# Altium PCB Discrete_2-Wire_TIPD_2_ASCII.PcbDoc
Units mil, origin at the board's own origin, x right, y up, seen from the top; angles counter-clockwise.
Board outline 1600 x 900 mil, 2 copper layers (Top Layer, Bottom Layer), stack 62 mil thick; 27 components, 16 nets, 69 pads, 21 vias.
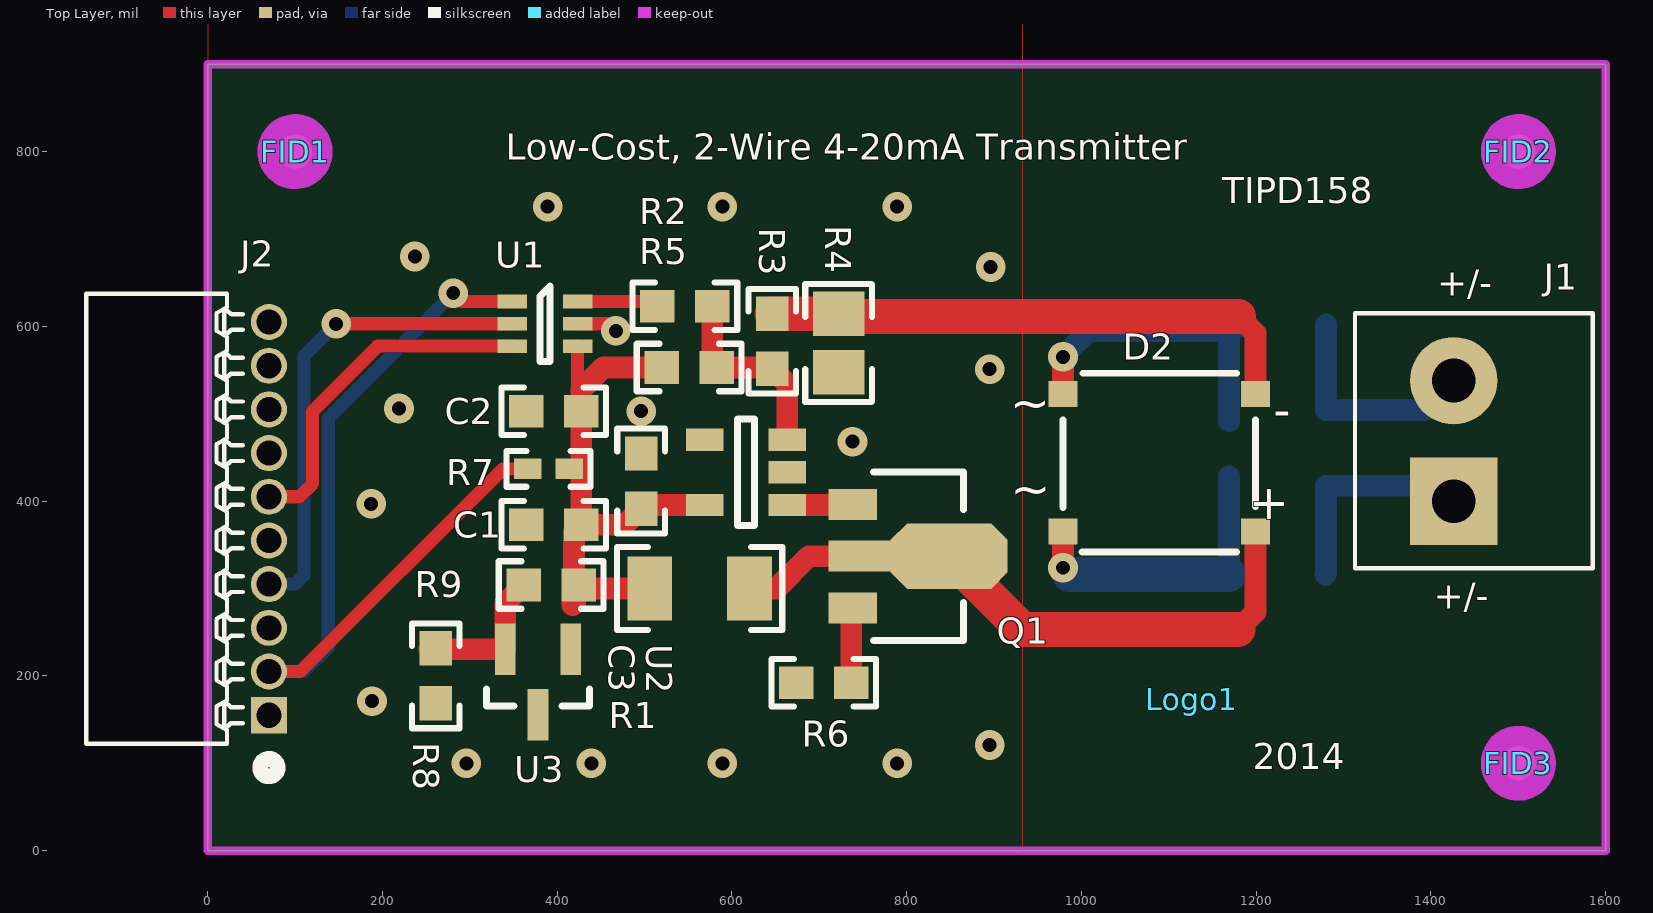
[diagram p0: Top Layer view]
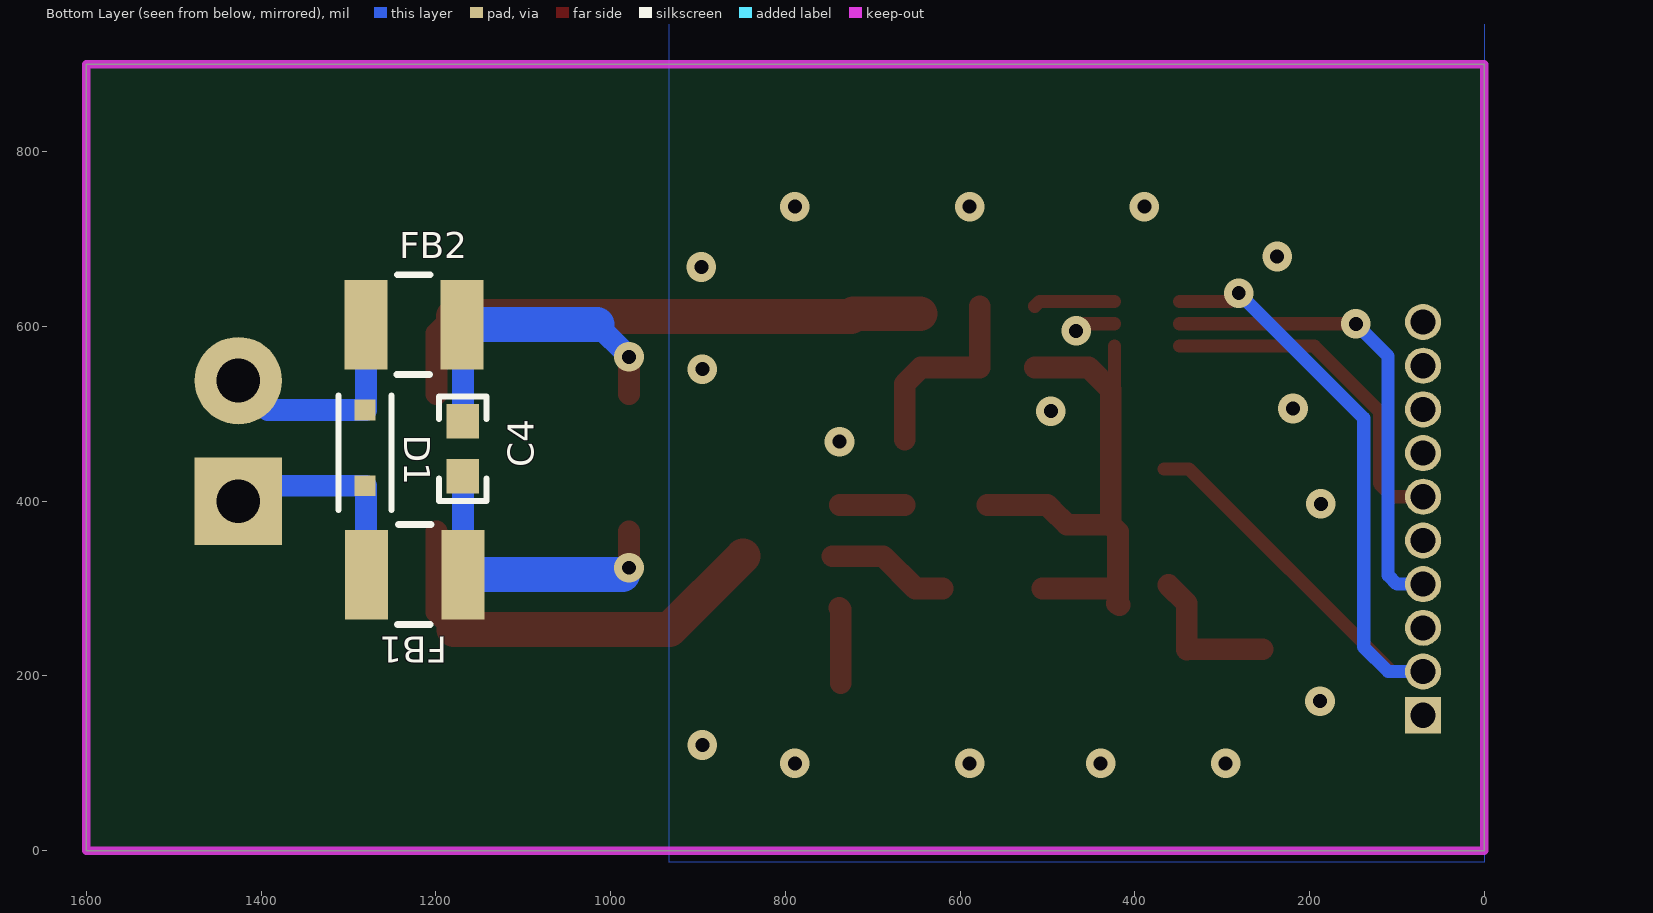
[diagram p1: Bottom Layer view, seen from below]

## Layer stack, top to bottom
Top Layer: signal copper 1.4
Dielectric: core 59.2, FR-4, Dk 4.8
Bottom Layer: signal copper 1.4

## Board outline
0,0 1600,0 1600,900 0,900

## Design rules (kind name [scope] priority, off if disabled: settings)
AcuteAngle [All] p0: scope1count=1 scope1_0_kind=Board scope1_0_value=Board scope2count=1 scope2_0_kind=Board scope2_0_value=Board commentlength=0 minimum=4.50000000000000E+0001
AcuteAngle [All] p1: minimum=4.50000000000000E+0001 checktracksonly=FALSE
AssemblyTestPointUsage [All] p0: scope1count=1 scope1_0_kind=Board scope1_0_value=Board scope2count=1 scope2_0_kind=Board scope2_0_value=Board commentlength=0
AssemblyTestPointUsage [All] p1: valid=2
AssemblyTestpoint [All] p0: scope1count=1 scope1_0_kind=Board scope1_0_value=Board scope2count=1 scope2_0_kind=Board scope2_0_value=Board commentlength=0
Clearance [All] p0: scope1count=1 scope1_0_kind=Board scope1_0_value=Board scope2count=1 scope2_0_kind=Board scope2_0_value=Board commentlength=0 gap=8
Clearance Clearance_Poly [All] p0 off: scope1count=1 scope1_0_kind=Board scope1_0_value=Board scope2count=1 scope2_0_kind=Board scope2_0_value=Board commentlength=48 gap=10 // Protel DXP Scope 1 Expression Was: InPolygon
Clearance Clearance_BoardEdge [All] p0 off: scope1count=1 scope1_0_kind=Board scope1_0_value=Board scope2count=1 scope2_0_kind=Board scope2_0_value=Board commentlength=48 gap=75 // Protel DXP Scope 2 Expression Was: IsKeepOut
Clearance Clearance_BoardEdge_Poly [All] p0 off: scope1count=1 scope1_0_kind=Board scope1_0_value=Board scope2count=1 scope2_0_kind=Board scope2_0_value=Board commentlength=48 gap=25 // Protel DXP Scope 2 Expression Was: IsKeepOut
Clearance Clearance_BoardEdge_MountingHoles [All] p0 off: scope1count=1 scope1_0_kind=Board scope1_0_value=Board scope2count=1 scope2_0_kind=Board scope2_0_value=Board commentlength=48 gap=40 // Protel DXP Scope 2 Expression Was: IsKeepOut
Clearance Clearance_BoardEdge_MountingHoles [OnCopper and InComponentClass('Mounting Holes') vs IsKeepOut] p1: gap=40
Clearance Clearance_BoardEdge_Poly [OnCopper and InPoly vs IsKeepOut] p2: gap=25
Clearance Clearance_BoardEdge [OnCopper and Not InComponentClass('Logo') and not InComponentClass('FiducialMark') and not InRegion(1000,500,4000,800) and Not IsKeepout vs IsKeepOut] p3: gap=75
Clearance Clearance_Poly [InPolygon] p4: gap=10
Clearance [All] p5: gap=8
ComponentClearance [All] p0: scope1count=1 scope1_0_kind=Board scope1_0_value=Board scope2count=1 scope2_0_kind=Board scope2_0_value=Board commentlength=0 gap=40 collisioncheckmode=3
ComponentClearance ComponentClearance_THtoTH [All] p0 off: scope1count=1 scope1_0_kind=Board scope1_0_value=Board scope2count=1 scope2_0_kind=Board scope2_0_value=Board commentlength=54 gap=118.11 collisioncheckmode=3 // Protel DXP Scope 2 Expression Was: IsThruComponent
ComponentClearance ComponentClearance_THtoSMT [All] p0 off: scope1count=1 scope1_0_kind=Board scope1_0_value=Board scope2count=1 scope2_0_kind=Board scope2_0_value=Board commentlength=53 gap=100 collisioncheckmode=3 // Protel DXP Scope 2 Expression Was: IsSMTComponent
ComponentClearance ComponentClearance_SmallPassives [All] p0 off: scope1count=1 scope1_0_kind=Board scope1_0_value=Board scope2count=1 scope2_0_kind=Board scope2_0_value=Board commentlength=508 gap=20 collisioncheckmode=3 // Protel DXP Scope 2 Expression Was: HasFootprint('0201*') or HasFootprint('0402*') or HasFootprint('0508') or HasFootprint('0603*') or HasFootprint('0612') or HasFootprint('0805*') or HasFootprint('0815*') or HasFootprint('0830*') or HasFootprint('1206*') or HasFootprint('1210*') or HasFootprint('1808*') or HasFootprint('1812*') or HasFootprint('1825*') or HasFootprint('2010*') or HasFootprint('2220*') or HasFootprint('2225*') or HasFootprint('2512*') or HasFootprint('2728*') or HasFootprint('3518*')
ComponentClearance ComponentClearance_MountingHoles [All] p0: scope1count=1 scope1_0_kind=ComponentClass scope1_0_value="Mounting Holes" scope2count=1 scope2_0_kind=Board scope2_0_value=Board commentlength=0 gap=250 collisioncheckmode=3
ComponentClearance ComponentClearance_ScrewToNut [All] p0 off: scope1count=1 scope1_0_kind=Board scope1_0_value=Board scope2count=1 scope2_0_kind=Board scope2_0_value=Board commentlength=71 gap=5 collisioncheckmode=3 // Protel DXP Scope 2 Expression Was: (HasFootprint('Keystone_1902C'))
ComponentClearance ComponentClearance_Logo [All] p0: scope1count=1 scope1_0_kind=ComponentClass scope1_0_value=Logo scope2count=1 scope2_0_kind=Board scope2_0_value=Board commentlength=0 gap=50 collisioncheckmode=3
ComponentClearance ComponentClearance_Shunt [All] p0: scope1count=1 scope1_0_kind=ComponentClass scope1_0_value=Header scope2count=1 scope2_0_kind=ComponentClass scope2_0_value=Shunt commentlength=0 gap=0 collisioncheckmode=3
ComponentClearance ComponentClearance_Shunt [InComponentClass('Header') vs InComponentClass('Shunt')] p1: gap=0 collisioncheckmode=3 verticalgap=0 showdistances=FALSE
ComponentClearance ComponentClearance_Logo [InComponentClass('Logo')] p2: gap=50 collisioncheckmode=3 verticalgap=10 showdistances=FALSE
ComponentClearance ComponentClearance_ScrewToNut [(HasFootprint('NY PMS 440 0025 PH')) vs (HasFootprint('Keystone_1902C'))] p3: gap=5 collisioncheckmode=3 verticalgap=10 showdistances=FALSE
ComponentClearance ComponentClearance_MountingHoles [InComponentClass('Mounting Holes')] p4: gap=250 collisioncheckmode=3 verticalgap=100000 showdistances=FALSE
ComponentClearance ComponentClearance_SmallPassives [HasFootprint('0201*') or HasFootprint('0402*') or HasFootprint('0508') or HasFootprint('0603*') or HasFootprint('0612') or HasFootprint('0805*') or HasFootprint('0815*') or HasFootprint('0830*') or HasFootprint('1206*') or HasFootprint('1210*') or HasFootprint('1808*') or HasFootprint('1812*') or HasFootprint('1825*') or HasFootprint('2010*') or HasFootprint('2220*') or HasFootprint('2225*') or HasFootprint('2512*') or HasFootprint('2728*') or HasFootprint('3518*') vs HasFootprint('0201*') or HasFootprint('0402*') or HasFootprint('0508') or HasFootprint('0603*') or HasFootprint('0612') or HasFootprint('0805*') or HasFootprint('0815*') or HasFootprint('0830*') or HasFootprint('1206*') or HasFootprint('1210*') or HasFootprint('1808*') or HasFootprint('1812*') or HasFootprint('1825*') or HasFootprint('2010*') or HasFootprint('2220*') or HasFootprint('2225*') or HasFootprint('2512*') or HasFootprint('2728*') or HasFootprint('3518*')] p5: gap=20 collisioncheckmode=3 verticalgap=10 showdistances=FALSE
ComponentClearance ComponentClearance_THtoSMT [IsThruComponent vs IsSMTComponent] p6: gap=100 collisioncheckmode=3 verticalgap=30 showdistances=FALSE
ComponentClearance ComponentClearance_THtoTH [IsThruComponent vs IsThruComponent] p7: gap=118.11 collisioncheckmode=3 verticalgap=30 showdistances=FALSE
ComponentClearance [All] p8: gap=40 collisioncheckmode=3 verticalgap=10 showdistances=FALSE
DiffPairsRouting [All] p0: scope1count=1 scope1_0_kind=Board scope1_0_value=Board scope2count=1 scope2_0_kind=Board scope2_0_value=Board commentlength=0
DiffPairsRouting [All] p1: maxlimit=100 minlimit=10 mostfreqgap=10 maxuncoupledlength=1000
FabricationTestPointUsage TestPointUsage [All] p0: scope1count=1 scope1_0_kind=Board scope1_0_value=Board scope2count=1 scope2_0_kind=Board scope2_0_value=Board commentlength=0 valid=2 allowmultiple=FALSE
FabricationTestPointUsage TestPointUsage [All] p1: valid=2 allowmultiple=FALSE
FabricationTestpoint Testpoint [All] p0: scope1count=1 scope1_0_kind=Board scope1_0_value=Board scope2count=1 scope2_0_kind=Board scope2_0_value=Board commentlength=0 side=3 testpointundercomponent=TRUE minsize=40 maxsize=100 preferedsize=60 minholesize=0 maxholesize=40 preferedholesize=32 testpointgrid=1
FabricationTestpoint Testpoint [All] p1: side=3 testpointundercomponent=TRUE minsize=40 maxsize=100 preferedsize=60 minholesize=0 maxholesize=40 preferedholesize=32 testpointgrid=1 allowsidetop=TRUE allowsidebottom=TRUE usegrid=TRUE gridtolerance=0.01
FanoutControl Fanout_Small [All] p0 off: scope1count=1 scope1_0_kind=Board scope1_0_value=Board scope2count=1 scope2_0_kind=Board scope2_0_value=Board commentlength=84 // Protel DXP Scope 1 Expression Was: (CompPinCount < 5)   Fanout_Small (Default Rule)
FanoutControl Fanout_Default [All] p0: scope1count=1 scope1_0_kind=Board scope1_0_value=Board scope2count=1 scope2_0_kind=Board scope2_0_value=Board commentlength=30 // Fanout_Default (Default Rule)
FanoutControl Fanout_SOIC [All] p0 off: scope1count=1 scope1_0_kind=Board scope1_0_value=Board scope2count=1 scope2_0_kind=Board scope2_0_value=Board commentlength=71 // Protel DXP Scope 1 Expression Was: IsSOIC   Fanout_SOIC (Default Rule)
FanoutControl Fanout_BGA [All] p0 off: scope1count=1 scope1_0_kind=Board scope1_0_value=Board scope2count=1 scope2_0_kind=Board scope2_0_value=Board commentlength=69 // Protel DXP Scope 1 Expression Was: IsBGA   Fanout_BGA (Default Rule)
FanoutControl Fanout_LCC [All] p0 off: scope1count=1 scope1_0_kind=Board scope1_0_value=Board scope2count=1 scope2_0_kind=Board scope2_0_value=Board commentlength=69 // Protel DXP Scope 1 Expression Was: IsLCC   Fanout_LCC (Default Rule)
FanoutControl Fanout_LCC [IsLCC] p1: bgadir=Out bgaviamode=Centered fanoutstyle=Auto fanoutdirection=Alternating viagrid=1 // Fanout_LCC (Default Rule)
FanoutControl Fanout_BGA [IsBGA] p2: bgadir=Out bgaviamode=Centered fanoutstyle=Auto fanoutdirection=Alternating viagrid=1 // Fanout_BGA (Default Rule)
FanoutControl Fanout_Default [All] p4: bgadir=Out bgaviamode=Centered fanoutstyle=Auto fanoutdirection=Alternating viagrid=1 // Fanout_Default (Default Rule)
FanoutControl Fanout_Small [(CompPinCount < 5)] p5: bgadir=Out bgaviamode=Centered fanoutstyle=Auto fanoutdirection=OutThenIn viagrid=1 // Fanout_Small (Default Rule)
Height [All] p0: scope1count=1 scope1_0_kind=Board scope1_0_value=Board scope2count=1 scope2_0_kind=Board scope2_0_value=Board commentlength=0
HoleSize [All] p0: scope1count=1 scope1_0_kind=Board scope1_0_value=Board scope2count=1 scope2_0_kind=Board scope2_0_value=Board commentlength=0 absolutevalues=TRUE maxlimit=251 minlimit=8 maxpercent=80.000 minpercent=20.000
HoleSize [All] p1: absolutevalues=TRUE maxlimit=251 minlimit=8 maxpercent=80.000 minpercent=20.000
HoleToHoleClearance [All] p0: scope1count=1 scope1_0_kind=Board scope1_0_value=Board scope2count=1 scope2_0_kind=Board scope2_0_value=Board commentlength=0
LayerPairs [All] p0: scope1count=1 scope1_0_kind=Board scope1_0_value=Board scope2count=1 scope2_0_kind=Board scope2_0_value=Board commentlength=0 enforce=TRUE
MinimumAnnularRing [All] p0: scope1count=1 scope1_0_kind=Board scope1_0_value=Board scope2count=1 scope2_0_kind=Board scope2_0_value=Board commentlength=0 minimumring=9
MinimumAnnularRing MinimumAnnularRing_ThermalPadVias [All] p0 off: scope1count=1 scope1_0_kind=Board scope1_0_value=Board scope2count=1 scope2_0_kind=Board scope2_0_value=Board commentlength=63 minimumring=5.91 // Protel DXP Scope 1 Expression Was: IsVia and InAnyComponent
MinimumAnnularRing MinimumAnnularRing_ThermalPadVias [IsVia and InAnyComponent] p1: minimumring=5.91
MinimumAnnularRing [All] p2: minimumring=9
MinimumSolderMaskSliver [All] p0: scope1count=1 scope1_0_kind=Board scope1_0_value=Board scope2count=1 scope2_0_kind=Board scope2_0_value=Board commentlength=0
MinimumSolderMaskSliver MinimumSolderMaskSliver_Logo [All] p0: scope1count=1 scope1_0_kind=ComponentClass scope1_0_value=Logo scope2count=1 scope2_0_kind=ComponentClass scope2_0_value=Logo commentlength=0
MinimumSolderMaskSliver MinimumSolderMaskSliver_Logo [InComponentClass('Logo') vs InComponentClass('Logo')] p1: minsoldermaskwidth=0.7
MinimumSolderMaskSliver [All] p2: minsoldermaskwidth=3.94
NetAntennae [All] p0: scope1count=1 scope1_0_kind=Board scope1_0_value=Board scope2count=1 scope2_0_kind=Board scope2_0_value=Board commentlength=0
PasteMaskExpansion [All] p0: scope1count=1 scope1_0_kind=Board scope1_0_value=Board scope2count=1 scope2_0_kind=Board scope2_0_value=Board commentlength=0 expansion=0
PlaneClearance [All] p0: scope1count=1 scope1_0_kind=Board scope1_0_value=Board scope2count=1 scope2_0_kind=Board scope2_0_value=Board commentlength=0 clearance=10
PlaneClearance [All] p1: clearance=10
PlaneConnect [All] p0: scope1count=1 scope1_0_kind=Board scope1_0_value=Board scope2count=1 scope2_0_kind=Board scope2_0_value=Board commentlength=0 planeconnectstyle=Relief reliefexpansion=10 reliefentries=4 reliefconductorwidth=10 reliefairgap=10
PlaneConnect [All] p1: planeconnectstyle=Relief reliefexpansion=10 reliefentries=4 reliefconductorwidth=10 reliefairgap=10
PolygonConnect PolygonConnect_1 [All] p0 off: scope1count=1 scope1_0_kind=Board scope1_0_value=Board scope2count=1 scope2_0_kind=Board scope2_0_value=Board commentlength=75 connectstyle=Relief reliefconductorwidth=15 reliefentries=4 polygonreliefangle="90 Angle" // Protel DXP Scope 1 Expression Was: (InComponentClass('All Components'))
PolygonConnect [All] p0: scope1count=1 scope1_0_kind=Board scope1_0_value=Board scope2count=1 scope2_0_kind=Board scope2_0_value=Board commentlength=0 connectstyle=Direct reliefconductorwidth=10 reliefentries=4 polygonreliefangle="90 Angle"
PolygonConnect PolygonConnect_1 [(InComponentClass('All Components'))] p1: connectstyle=Relief reliefconductorwidth=15 reliefentries=4 polygonreliefangle="90 Angle" airgapwidth=10
PolygonConnect [All] p2: connectstyle=Direct reliefconductorwidth=10 reliefentries=4 polygonreliefangle="90 Angle" airgapwidth=10
RoutingCorners [All] p0: scope1count=1 scope1_0_kind=Board scope1_0_value=Board scope2count=1 scope2_0_kind=Board scope2_0_value=Board commentlength=0 cornerstyle=45-Degree minsetback=100 maxsetback=100
RoutingLayers [All] p0: scope1count=1 scope1_0_kind=Board scope1_0_value=Board scope2count=1 scope2_0_kind=Board scope2_0_value=Board commentlength=0 top layer=Automatic bottom layer=Automatic
RoutingPriority [All] p0: scope1count=1 scope1_0_kind=Board scope1_0_value=Board scope2count=1 scope2_0_kind=Board scope2_0_value=Board commentlength=0
RoutingTopology [All] p0: scope1count=1 scope1_0_kind=Board scope1_0_value=Board scope2count=1 scope2_0_kind=Board scope2_0_value=Board commentlength=0 topology=Shortest
RoutingVias [All] p0: scope1count=1 scope1_0_kind=Board scope1_0_value=Board scope2count=1 scope2_0_kind=Board scope2_0_value=Board commentlength=0 holewidth=16 width=34 viastyle="Through Hole" minholewidth=7.87 minwidth=26 maxholewidth=40 maxwidth=65
RoutingVias ThermalPadVias [All] p0 off: scope1count=1 scope1_0_kind=Board scope1_0_value=Board scope2count=1 scope2_0_kind=Board scope2_0_value=Board commentlength=63 holewidth=7.87 width=19.68 viastyle="Through Hole" minholewidth=7.87 minwidth=19.68 maxholewidth=12.99 maxwidth=23.62 // Protel DXP Scope 1 Expression Was: IsVia and InAnyComponent
RoutingVias ThermalPadVias [IsVia and InAnyComponent] p1: holewidth=7.87 width=19.68 viastyle="Through Hole" minholewidth=7.87 minwidth=19.68 maxholewidth=12.99 maxwidth=23.62
RoutingVias [All] p2: holewidth=16 width=34 viastyle="Through Hole" minholewidth=7.87 minwidth=26 maxholewidth=40 maxwidth=65
SMDToCorner [All] p0: scope1count=1 scope1_0_kind=Board scope1_0_value=Board scope2count=1 scope2_0_kind=Board scope2_0_value=Board commentlength=0 distance=30000
SMDToCorner [All] p1: distance=30000
ShortCircuit [All] p0: scope1count=1 scope1_0_kind=Board scope1_0_value=Board scope2count=1 scope2_0_kind=Board scope2_0_value=Board commentlength=0 allowed=FALSE
SilkToSilkClearance [All] p0: scope1count=1 scope1_0_kind=Board scope1_0_value=Board scope2count=1 scope2_0_kind=Board scope2_0_value=Board commentlength=0
SilkToSilkClearance [All] p1: silktosilkclearance=5
SilkscreenOverComponentPads [All] p0: scope1count=1 scope1_0_kind=Board scope1_0_value=Board scope2count=1 scope2_0_kind=Board scope2_0_value=Board commentlength=0
SilkscreenOverComponentPads [All] p1: minsilkscreentomaskgap=5
SolderMaskExpansion [All] p0: scope1count=1 scope1_0_kind=Board scope1_0_value=Board scope2count=1 scope2_0_kind=Board scope2_0_value=Board commentlength=0 expansion=1.97
SolderMaskExpansion [All] p1: expansion=1.97
UnRoutedNet [All] p0: scope1count=1 scope1_0_kind=Board scope1_0_value=Board scope2count=1 scope2_0_kind=Board scope2_0_value=Board commentlength=0
Width [All] p0: scope1count=1 scope1_0_kind=Board scope1_0_value=Board scope2count=1 scope2_0_kind=Board scope2_0_value=Board commentlength=0 maxlimit=100 minlimit=6 preferedwidth=10
Width [All] p1: maxlimit=100 minlimit=6 preferedwidth=10 checkconnectedcopper=TRUE
13 further rules are at their usual default settings.

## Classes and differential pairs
component class Discrete_2-Wire_AO_2: C1 C2 C3 C4 D1 D2 FB1 FB2 J1 J2 Q1 R1 R2 R3 R4 R5 R6 R7 R8 U1 U2 U3
component class FiducialMark: FID1 FID2 FID3
component class Hardware_ANSI-B: FID1 FID2 FID3 Logo1
component class Logo: Logo1

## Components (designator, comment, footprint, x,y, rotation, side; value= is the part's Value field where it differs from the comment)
C1 "CC0603ZRY5V6BB225" 0603 396.02,373 r180 top
C2 "CC0603KRX7R0BB104" 0603 396.02,503 r180 top
C3 "CC0603KRX7R0BB104" 0603 496.02,423 r90 top
C4 "C1608X7R2A472K080AA" 0603 1169,460 r90 bottom
D1 "CDSOD323-T36SC" sod-323 1281,461 r90 bottom
D2 "DSRHD10-13" T-MiniDIP 1089,444 r180 top
FB1 "FBMH3225HM601NT" 1210_H25 1224,316 r0 bottom
FB2 "FBMH3225HM601NT" 1210_H25 1225,602 r0 bottom
FID1 "Fiducial" Fiducial10-20 100,800 r0 top
FID2 "Fiducial" Fiducial10-20 1500,800 r0 top
FID3 "Fiducial" Fiducial10-20 1500,100 r0 top
J1 "ED555/2DS" TERM_BLK_ED555-2DS 1426,400 r90 top
J2 "SUPER MINI DIG FEMALE" CONN_851-43-010-20-001000 70,380 r270 top
Logo1 "Texas Instruments" TI_Symbol_Overlay_Small 1126,173 r0 top
Q1 "FCX690BTA" SOT-89-3 813,337 r0 top
R1 "RC1206FR-077K15L" 1206 563,300 r180 top
R2 "ERA-3AEB3092V" 0603 546.02,623 r0 top
R3 "ERA-3AEB4321V" 0603 646.02,583 r270 top
R4 "RP73PF2A44R2BTDF" 0805 722,581 r270 top
R5 "ERA-3AEB1243V" 0603 551,553 r180 top
R6 "CRCW060320R0FKEA" 0603 705,192 r0 top
R7 "CRCW040210K0FKED" 0402 390,437 r0 top
R8 "TNPW060324K9BEEA" 0603 393,304 r0 top
R9 "TNPW060324K9BEEA" 0603 261,200 r90 top
U1 "DAC7311IDCK" DCK0006A_N 386.02,603 r0 top
U2 "OPA317IDBV" DBV0005A_N 616.02,433 r180 top
U3 "TL431BQDBZ" DBZ0003A_N 378,193 r270 top

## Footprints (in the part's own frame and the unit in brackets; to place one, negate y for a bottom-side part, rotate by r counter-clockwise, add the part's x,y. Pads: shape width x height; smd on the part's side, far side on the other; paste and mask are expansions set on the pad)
0402 [mm] "0402 from SM-752 data"
  rect 0.8x0.6 smd: 1(-0.6,0) 2(0.6,0)
  silkscreen extent -1.22,-0.52 1.22,0.52
0603 [mm] "0603 from SM-752 data"
  rect 1x0.95 smd: 1(-0.8,0) 2(0.8,0)
  silkscreen extent -1.52,-0.69 1.52,0.69
0805 [mm] "0805 from SM-752 data"
  rect 1.3x1.5 smd: 1(-0.85,0) 2(0.85,0)
  silkscreen extent -1.72,-0.97 1.72,0.97
1206 [mm] "1206 from SM-752 data"
  rect 1.3x1.85 smd: 1(-1.45,0) 2(1.45,0)
  silkscreen extent -2.4,-1.21 2.4,1.21
1210_H25 [mm]
  rect 1.25x2.6 smd: 1(-1.4,0) 2(1.4,0)
  silkscreen extent -0.47,-1.45 0.5,1.45
CONN_851-43-010-20-001000 [mm] "Mill-max"
  rect 1.05x1.05 hole 0.73 mask+0.06: 1(5.715,0)
  round 1.05 hole 0.73 mask+0.06: 2(4.445,0) 3(3.175,0) 4(1.905,0) 5(0.635,0) 6(-0.635,0) 7(-1.905,0) 8(-3.175,0) 9(-4.445,0) 10(-5.715,0)
  silkscreen extent -6.54,-5.31 7.49,0.25
DBV0005A_N [mm] "SOT23, 5-Leads, Body 2.9x1.6mm, Pitch 0.95mm, Lead Span 2.8mm, IPC Medium Density"
  rect 1.1x0.65 smd: 1(-1.2,0.95) 2(-1.2,0) 3(-1.2,-0.95) 4(1.2,-0.95) 5(1.2,0.95)
  silkscreen extent -0.25,-1.55 0.25,1.55
DBZ0003A_N [mm] "SOT23, 3-Leads, Body 2.9x1.3mm, Pitch 0.95mm, Lead Span 2.4mm, IPC Medium Density"
  rect 1.5x0.6 smd: 1(-0.95,0.95) 2(-0.95,-0.95) 3(0.95,0)
  silkscreen extent 0.2,-1.5 0.7,1.5
DCK0006A_N [mm] "SOT23, 6-Leads, Body 2x1.3mm, Pitch 0.65mm, Lead Span 2.1mm, IPC Medium Density"
  rect 0.85x0.4 smd: 1(-0.95,0.65) 2(-0.95,0) 3(-0.95,-0.65) 4(0.95,-0.65) 5(0.95,0) 6(0.95,0.65)
  silkscreen extent -0.15,-1.1 0.15,1.1
Fiducial10-20 [mm]
  round 1 smd paste-0.5 mask+0.5: 1(0,0)
  Top Layer keep-out circle w1.178: c0,0 r0.5
sod-323 [mm] "NXP recommended land pattern"
  rect 0.6x0.6 smd paste-0.05: 1(-1.1,0) 2(1.1,0)
  silkscreen extent -1.8,-0.77 1.53,0.77
SOT-89-3 [mm] "SOT, 3-Leads, Body 4.6 x 2.6 mm, Pitch 1.5mm"
  rect 1.4x0.9 smd: 1(-1.9,1.5) 3(-1.9,-1.5)
  rect 1.8x0.9 smd: 2(-1.7,0)
  oct 3.4x1.9 smd: 4(0.9,0)
  silkscreen extent -1.3,-2.45 1.33,2.45
T-MiniDIP [mm] "DIODES INC"
  rect 0.85x0.75 smd: 1(-2.8,2) 2(-2.8,-2) 3(2.8,-2) 4(2.8,2)
  silkscreen extent -2.8,-2.6 2.8,2.6
TERM_BLK_ED555-2DS [mil]
  rect 100x100 hole 50: 1(0,0)
  round 100 hole 50: 2(138,0)
  silkscreen extent -77,-159 215,113
TI_Symbol_Overlay_Small [mil]

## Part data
C1: library part Capacitor, "CAP CER 2.2UF 10V Y5V 0603"
C2 C3: library part Capacitor, "CAP CER 0.1UF 100V 10% X7R 0603"
C4: library part Capacitor, "CAP CER 4700PF 100V 10% X7R 0603"
D1: library part SMAJ15CA, "TVS DIODE 36VWM 60VC SOD323"
D2: "Diode, Switching-Bridge, 1000V, 1A, 5.0x1.21x6.2mm"
FB1 FB2: "3A Ferrite Bead, 600 ohm @ 100MHz, SMD"
FID1 FID2 FID3: "Fiducial mark.  There is nothing to buy or mount."
J1: "Terminal Block, 6A, 3.5mm Pitch, 2-Pos, TH"
J2: library part 851-43-010-20-001000, "Receptacle, 50mil 10x1, R/A, TH"
Logo1: library part TI_Logo, "Texas Instrument Corporate Signature"
Q1: library part "FCX690BTA, Diodes Inc.", "Transistor, NPN, 45V, 1A, SOT-89"
R1: library part Resistor, "RES 7.15K OHM 1/4W 1% 1206 SMD"
R2: library part Resistor, "RES 30.9K OHM 1/10W .1% 0603 SMD"
R3: library part Resistor, "RES 4.32K OHM 1/10W .1% 0603 SMD"
R4: library part Resistor, "RES 44.2 OHM 1/4W 0.1% 0805"
R5: library part Resistor, "RES 124K OHM 1/10W .1% 0603 SMD"
R6: "RES, 20.0 ohm, 1%, 0.1W, 0603"
R7: "RES, 10.0k ohm, 1%, 0.063W, 0402"
R8 R9: library part Resistor, "RES 24.9K OHM 1/10W 0.1% 0603"
U1: "2.0V to 5.5V, 80µA, 12-Bit, Low-Power, Single-Channel, Digital-to-Analog Converters in SC70 Package, DCK0006A"
U2: "Low-Offset, Rail-to-Rail I/O Operational Amplifier, DBV0005A"
U3: "PRECISION PROGRAMMABLE REFERENCE, DBZ0003A"

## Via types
v1: diameter 34, hole 16, Top Layer to Bottom Layer, 21 vias

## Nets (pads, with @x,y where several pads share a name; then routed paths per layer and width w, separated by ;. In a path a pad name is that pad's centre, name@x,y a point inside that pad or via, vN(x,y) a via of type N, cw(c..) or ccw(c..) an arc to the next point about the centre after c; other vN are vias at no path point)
+5V: C1.1 C2.1 C3.1 R1.2 R5.2 R7.2 R8.2 U1.4 U2.5 U3.1 | length 663.9
  Top Layer w15: U1.4 423.42,507.09 C2.1
  Top Layer w25: 417.62,281.3 419.32,283 ; 420.31,283 419.32,283 ; R1.2 423.32,300 R8.2@419.32,304 ; R5.2@514.52,553 452.82,553 427.51,527.7 C2.1 C1.1 ; U2.5 500.11,395.6 C3.1 477.51,373 C1.1 ; 419.32,283 R8.2@419.32,304 ; R8.2@419.32,304 419.32,364.81 C1.1
GND: C1.2 C2.2 C3.2 J2.3 R4.2 R6.1 R9.1 U1.5 U2.2 U2.4 U3.3 | length 46.9
  Top Layer w15: U1.5 459,603 v1(467,595)
  other v1: 296,100 439,100 589,100 789,100 895,121 188,171 187,397 738,468 496,503 219,506 895,551 896,668 237,680 389,737 589,737 789,737
NetC4_1: C4.1 D2.4 FB1.1 | length 347.4
  Top Layer w25: v1(978.76,323.76) D2.4
  Bottom Layer w25: v1(978.76,323.76) v1@986.53,316 ; FB1.1 1169,316.12 C4.1
  Bottom Layer w40: v1@986.53,316 FB1.1
NetC4_2: C4.2 D2.3 FB2.1 | length 359.7
  Top Layer w25: D2.3 v1(978.76,565.24)
  Bottom Layer w25: v1(978.76,565.24) 1015.53,602 ; C4.2 1169,601.12 FB2.1
  Bottom Layer w40: 1015.53,602 FB2.1
NetD1_1: D1.1 FB1.2 J1.1 | length 301.6
  Top Layer w25: J1.1@1403.31,413.69 J1.1@1419,398
  Bottom Layer w25: FB1.2 1280,316.88 D1.1@1280,417.69 ; D1.1 1408.31,417.69 J1.1 ; J1.1@1401.31,415.69 J1.1@1419,398
NetD1_2: D1.2 FB2.2 J1.2 | length 257.7
  Bottom Layer w25: FB2.2 1280,601.88 1280,504.31 1392.31,504.31 J1.2
NetD2_1: D2.1 Q1.2 Q1.4 R1.1 | length 627.3
  Top Layer w25: R1.1 651,300 688,337 Q1.2 ; 1179,253 1199.24,273.24 D2.1
  Top Layer w40: Q1.4 932.43,253 1179,253
NetD2_2: D2.2 R3.1 R4.1 | length 631.6
  Top Layer w25: 1179.54,611.46 1199.24,591.76 D2.2
  Top Layer w40: R3.1 R4.1 ; R4.1 725,611.46 1179.54,611.46
NetJ2_2: J2.2 R7.1 U1.1 | length 1007.8
  Top Layer w15: J2.2 106,205 338,437 R7.1 ; v1(281,638) 290.41,628.59 U1.1
  Bottom Layer w15: J2.2 110,205 138,233 138,495 v1(281,638)
NetJ2_4: J2.4 U1.2 | length 549.1
  Top Layer w15: v1(147,603) U1.2
  Bottom Layer w15: J2.4 100,305 110,315 110,566 v1(147,603)
NetJ2_6: J2.6 U1.3 | length 381.2
  Top Layer w15: J2.6@87.5,405 105,405 120,420 120,503 194.41,577.41 U1.3
NetQ1_1: Q1.1 U2.1 | length 74.5
  Top Layer w25: U2.1 Q1.1@737.74,395.6
NetQ1_3: Q1.3 R6.2 | length 86.6
  Top Layer w25: R6.2 736.5,276.24 Q1.3
NetR2_1: R2.1 U1.6 | length 93.4
  Top Layer w15: U1.6 508.93,628.59 R2.1
NetR2_2: R2.2 R3.2 R5.1 U2.3 | length 225.3
  Top Layer w25: R2.2 577.51,553 R5.1 R3.2@644.52,553 ; R3.2 663.26,534.26 U2.3
NetR8_1: R8.1 R9.2 U3.2 | length 168.9
  Top Layer w15: U3.2@340.5,230.5 U3.2
  Top Layer w25: R9.2@254,230.5 U3.2@340.5,230.5 ; U3.2 340.6,283.09 R8.1
pads on no net: FID1.1 FID2.1 FID3.1 J2.1 J2.5 J2.7 J2.8 J2.9 J2.10

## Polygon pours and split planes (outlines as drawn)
GND on Bottom Layer "Bottom Layer-No Net" (solid, remove dead copper, pour order 4): 0,-13 933,-13 933,1000 0,1000
GND on Top Layer "Top Layer-No Net" (solid, remove dead copper, pour order 2): 0,-1 933,-1 933,1000 0,1000

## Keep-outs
Keep-Out Layer:
  the board outline again, w10

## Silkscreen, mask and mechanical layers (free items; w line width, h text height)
Top Overlay:
  text "Low-Cost, 2-Wire 4-20mA Transmitter" at 341,791 h30
  text "TIPD158" at 1161,741 h30
  text "+/-" at 1407,635 h30
  text "+/-" at 1403,277 h30
  text "2014" at 1196,93 h30
M1 Board Outline:
  the board outline again, w10
M2 Board Dimensions:
  rectangle: 124.5,-410.5 499.5,-285.5
  rectangle: -0.5,-285.5 124.5,-160.5
  lines w7: -0.5,-285.5 999.5,-285.5 ; 124.5,-410.5 124.5,-160.5 ; 249.5,-410.5 249.5,-160.5 ; 499.5,-410.5 499.5,-160.5 ; 749.5,-410.5 749.5,-160.5 ; -0.5,-410.5 -0.5,-160.5 999.5,-160.5 999.5,-410.5 -0.5,-410.5
  lines w10: 0,900 1600,900 ; 0,1000 0,0 1600,0 1600,1000
M5 Assembly Top:
  lines w10: -292,-930.17 6308,-930.17 ; -292,-726.83 6310,-726.83 ; -292,-523.5 -292,-1133.5 3713,-1133.5 6310,-1133.5 6310,-523.5 -291.5,-523.5 -291.5,-1133.5 1284,-1133.5 ; 2173,-1133.5 2173,-523.5 ; 3440,-726.83 3440,-523.5 ; 4280,-726.83 4280,-523.5 ; 4902,-1140 4902,-937.17
  text "COMPONENTS MARKED 'DNP' SHOULD NOT BE POPULATED." at 1153.5,-318.5 h60
  text "ASSEMBLY VARIANT:" at 1153,-434 h60
  text ".VariantName" at 2189,-434 h60
  text "PCB VIEWED FROM TOP SIDE" at -228.5,-655.67 h60
  text "BOARD #:" at 2248,-655.67 h60
  text ".PRJ_Number" at 2793.5,-655.67 h60
  text "REV:" at 3638,-655.67 h60
  text ".PCB_Rev" at 3929.5,-655.67 h60
  text "SVN REV:" at 4476,-655.67 h60
  text ".VersionControl_RevNumber" at 4982,-655.67 h60
  text "IGNORE ->" at -228.5,-858.49 h60
  text "PLOT NAME =" at -228.5,-1064.34 h60
  text ".plot_File_Name" at 577,-1064.34 h60
  text "GENERATED    :" at 2250,-1064.34 h60
  text ".Print_Date" at 3119.5,-1064.34 h60
  text ".Print_Time" at 3848.5,-1064.34 h60
  text "TEXAS INSTRUMENTS" at 5113,-1064.34 h60
M6 Assembly Bottom:
  lines w10: -292.5,-727.33 6309.5,-727.33 ; -290.5,-930.67 6309.5,-930.67 ; 1115.5,-1140.5 1115.5,-937.67 ; 1737.5,-727.33 1737.5,-524 ; 2577.5,-727.33 2577.5,-524 ; 3844.5,-1134 3844.5,-524 ; 4733.5,-1134 6309,-1134 6309,-524 -292.5,-524 -292.5,-1134 2304.5,-1134 6309.5,-1134 6309.5,-524
  text "COMPONENTS MARKED 'DNP' SHOULD NOT BE POPULATED." at 6102,-318 h60
  text ".VariantName" at 5058,-434 h60
  text "ASSEMBLY VARIANT:" at 6097,-434 h60
  text ".VersionControl_RevNumber" at 1035.5,-656.17 h60
  text "SVN REV:" at 1541.5,-656.17 h60
  text ".PCB_Rev" at 2088,-656.17 h60
  text "REV:" at 2379.5,-656.17 h60
  text ".PRJ_Number" at 3224,-656.17 h60
  text "BOARD #:" at 3769.5,-656.17 h60
  text "PCB VIEWED FROM BOTTOM SIDE" at 6246,-656.17 h60
  text "IGNORE ->" at 2547.85,-858.49 h60
  text "TEXAS INSTRUMENTS" at 904.5,-1064.84 h60
  text ".Print_Time" at 2169,-1064.84 h60
  text ".Print_Date" at 2898,-1064.84 h60
  text "GENERATED    :" at 3767.5,-1064.84 h60
  text ".plot_File_Name" at 5440.5,-1064.84 h60
  text "PLOT NAME =" at 6246,-1064.84 h60
M9 Title Sheet:
  lines w10: -491.5,1041.5 -291.5,1041.5 ; -491.5,3416.5 -291.5,3416.5 ; -491.5,5791.5 -291.5,5791.5 ; 2008.5,-1333.5 2008.5,-1133.5 ; 2008.5,7966.5 2008.5,8166.5 ; 4508.5,-1333.5 4508.5,-1133.5 ; 4508.5,7966.5 4508.5,8166.5 ; 6321,-1133.5 6321,-523.5 11303.5,-523.5 ; 7008.5,-1333.5 7008.5,-1133.5 ; 7008.5,7966.5 7008.5,8166.5 ; 9508.5,-1333.5 9508.5,-1133.5 ; 9508.5,7966.5 9508.5,8166.5 ; 11303.5,-1133.5 11303.5,-523.5 ; 11303.5,-823.5 14303.5,-823.5 ; 11303.5,-223.5 14303.5,-223.5 ; 11304.5,370.5 14304.5,370.5 ; 12008.5,-1333.5 12008.5,-1133.5 ; 12008.5,7966.5 12008.5,8166.5 ; 12808.5,-1123.5 12808.5,-523.5 ; 14303.5,-523.5 11303.5,-523.5 ; 14303.5,76.5 11303.5,76.5 ; 14308.5,66.5 14308.5,-1133.5 ; 14308.5,871 11304.5,871 11303.5,871 11303.5,370.5 11303.5,76.5 ; 14308.5,1041.5 14508.5,1041.5 ; 14308.5,3416.5 14508.5,3416.5 ; 14308.5,5791.5 14508.5,5791.5 ; 11303.5,-523.5 11303.5,76.5 ; 14308.5,-1133.5 -291.5,-1133.5 -291.5,7966.5 14308.5,7966.5 14308.5,-1133.5 ; -491.5,-1333.5 14508.5,-1333.5 14508.5,8166.5 -491.5,8166.5 -491.5,-1333.5
  text "1" at 739.84,8036.5 h70
  text "2" at 3235.5,8036.5 h70
  text "3" at 5724.84,8036.5 h70
  text "4" at 8231.51,8036.5 h70
  text "5" at 10730.5,8036.5 h70
  text "6" at 13235.5,8036.5 h70
  text "A" at -416.5,6893.5 h70
  text "A" at 14383.5,6893.5 h70
  text "B" at -416.5,4513.5 h70
  text "B" at 14383.5,4513.5 h70
  text "C" at -416.5,2138.5 h70
  text "C" at 14383.5,2138.5 h70
  text "PROJECT TITLE:" at 11343.5,277.5 h45
  text ".PRJ_Title" at 11393.5,144.17 h70
  text "DESIGNED FOR:" at 11343.5,-23.5 h45
  text ".PRJ_Customer" at 11393.5,-163.5 h70
  text "D" at -416.5,-231.5 h70
  text "D" at 14383.5,-231.5 h70
  text "FILE NAME:" at 11343.5,-323.5 h45
  text ".PCB_File_Name_No_Path" at 11393.5,-443.5 h70
  text "Texas Instruments (TI) and/or its licensors do not warrant the accuracy or completeness of this specification" at 6374,-605.34 h45
  text "ENGINEER:" at 11343.5,-613.5 h45
  text "LAYOUT BY:" at 12848.5,-613.5 h45
  text "or any information contained therein. TI and/or its licensors do not warrant that this design will meet" at 6329.01,-718 h45
  text ".PRJ_Engineer" at 11393.5,-768.49 h70
  text ".PCB_Layout" at 12899,-768.49 h70
  text "the specifications, will be suitable for your application or fit for any particular purpose, or will operate in" at 6329.01,-830.67 h45
  text ".Layer_Name" at 577,-858.49 h60
  text "ALTIUM DESIGNER VERSION:" at 12848.5,-923.5 h45
  text "an implementation. TI and/or its licensors do not warrant that the design is production worthy. You should" at 6329.01,-943.33 h45
  text "completely validate and test your design implementation to confirm the system functionality for your application." at 6374,-1056 h45
  text ".print_Scale" at 11393.5,-1056.83 h70
  text ".Application_BuildNumber" at 12899,-1056.83 h70
  text "1" at 739.84,-1263.5 h70
  text "2" at 3235.5,-1263.5 h70
  text "3" at 5724.84,-1263.5 h70
  text "4" at 8231.51,-1263.5 h70
  text "5" at 10730.5,-1263.5 h70
  text "6" at 13235.5,-1263.5 h70
M10 Fab Notes:
  drawing of 212 lines, arcs and shapes, not listed
  text "DESIGN INFORMATION" at 12381.02,6810 h60
  text "(REFER ALSO ARRAY/PANEL PROFILING INFORMATION)" at 12019.46,6648.29 h60
  text "BOARD SIZE" at 11333.46,6644 h60
  text "900MIL" at 11795.78,6516.18 h60
  text "X" at 12301.46,6516.18 h60
  text "1500MIL" at 12532.78,6516.18 h60
  text "Number of Layers :" at 11736.46,6319 h60
  text "2" at 12831.27,6309 h60
  text "MIN. TRACK WIDTH:" at 11736.46,6180 h60
  text "8" at 12832.7,6180 h60
  text "MIL" at 12987.46,6180 h60
  text "MIN. CLEARANCE:" at 11736.46,6048 h60
  text "8" at 12832.7,6048 h60
  text "MIL" at 12987.46,6048 h60
  text "MIN. VIA PAD SIZE:" at 11736.46,5916 h60
  text "24" at 12802.71,5916 h60
  text "MIL" at 12987.46,5916 h60
  text "0.05mm (2MIL)" at 12431.46,5774.29 h60
  text "MINIMUM ANNULAR RING" at 11407.23,5770 h60
  text "EXTERNAL" at 13139.46,5770 h60
  text "PER" at 11607.23,5652 h60
  text "IPC-D-275 CLASS 2 LEVEL C" at 11827.23,5652 h60
  text "MIL, HOLES" at 13315.46,5539.71 h60
  text "+/-" at 12923,5539 h60
  text "+/-" at 13777,5539 h60
  text "REGISTRATION TOLERANCES:" at 11407.23,5534 h60
  text "METAL" at 12607,5534 h60
  text "5" at 13183.2,5534 h60
  text "3" at 14016.2,5534 h60
  text "MIL" at 14132.46,5534 h60
  text "MATERIAL:" at 11332.46,5324.54 h60
  text "FR-4 High Tg" at 12318.9,5184.21 h60
  text "FR-408" at 11753.46,5175.64 h60
  text "X" at 12165.46,5175.64 h60
  text "OTHER" at 13241.46,5175.64 h60
  text "62 MIL (1.6mm) +/-10%" at 12073.56,5012.92 h60
  text "THICKNESS:" at 11407.23,5008.64 h60
  text "X" at 11945.4,5008.64 h60
  text "OTHER" at 13358.46,5008.64 h60
  text "TOLERANCE:" at 11407.23,4850.64 h60
  text "X" at 12246.53,4850.64 h60
  text "ANSI IPC-6012 TYPE 3 CLASS 2" at 12433.48,4850.64 h60
  text "OTHER +/-" at 12433.46,4694.64 h60
  text "BOW & TWIST:" at 11407.23,4537.64 h60
  text "X" at 12246.53,4537.64 h60
  text "ANSI IPC-6012 TYPE 3 CLASS 2" at 12433.48,4537.64 h60
  text "OTHER +/-" at 12433.46,4379.13 h60
  text "COPPER THICKNESS (FINISHED):" at 11332.46,4243.64 h60
  text "1.4MIL (1oz)" at 12212.46,4090.92 h60
  text "2MIL (1.4oz)" at 12979.46,4090.92 h60
  text "2.8MIL (2oz)" at 13706.46,4090.92 h60
  text "OUTER:" at 11689.46,4086.64 h60
  text "X" at 12084,4086 h60
  text "1.4MIL (1oz)" at 12212.46,3933.92 h60
  text "2.8MIL (2oz)" at 12979.46,3933.92 h60
  text "N/A" at 13706,3934.29 h60
  text "INNER SIGNAL:" at 11400.38,3929.64 h60
  text "X" at 12085.42,3929.64 h60
  text "DRILLING:" at 11332.46,3790.64 h60
  text "REFERENCE:" at 11407.23,3673.64 h60
  text "X" at 12055.46,3673.64 h60
  text "AS SHOWN" at 12242.46,3673.64 h60
  text "X" at 12956.46,3673.64 h60
  text "NC_DRILL FILES" at 13093.46,3673.64 h60
  text "PTH MIN COPPER THICKNESS:" at 11407.23,3515.64 h60
  text "X" at 12757.46,3515.64 h60
  text "1MIL" at 12894.46,3515.64 h60
  text "OTHER" at 13391.46,3515.64 h60
  text "BOARD FINISH:" at 11332.46,3356.64 h60
  text "SILKSCREEN:" at 11487.68,3238.64 h60
  text "X" at 12436.46,3238.64 h60
  text "TOP" at 12562.46,3238.64 h60
  text "X" at 12946.46,3238.64 h60
  text "BOTTOM" at 13073.46,3238.64 h60
  text "SILKSCREEN COLOR:" at 11487.68,3071.64 h60
  text "X" at 12435.42,3071.64 h60
  text "WHITE" at 12562.46,3071.64 h60
  text "OTHER" at 13073.46,3071.64 h60
  text "SOLDER RESIST COLOR:" at 11487.68,2901.64 h60
  text "X" at 12055.42,2742.44 h60
  text "GREEN" at 12182.46,2742.44 h60
  text "BLUE" at 12773.46,2742.44 h60
  text "OTHER" at 13311.46,2742.44 h60
  text "IMMERSION GOLD (ENIG)" at 12393.46,2553.92 h60
  text "ENEPIG" at 13731,2550.64 h60
  text "SURFACE FINISH:" at 11332.46,2549.64 h60
  text "X" at 12206.51,2549.64 h60
  text "IMM. TIN/SILVER OR EQUIV" at 11662,2392.64 h60
  text "OTHER" at 13093.46,2392.64 h60
  text "ARRAY/PANEL:" at 11332.46,2213.64 h60
  text "CUT AND TRIM PER MECH LAYER 1" at 12393.46,2209.35 h60
  text "N.C. ROUTE" at 12393.46,2057.64 h60
  text "X" at 13072.46,2057.64 h60
  text "V. SCORE" at 13259.46,2057.64 h60
  text "CERTIFICATION:" at 11332.46,1920.64 h60
  text "MATERIALS AND WORKMANSHIP FOR ALL PCBS" at 12057.46,1920.64 h60
  text "TO MEET OR EXCEED THE REQUIREMENTS OF:" at 12057.46,1822.64 h60
  text "X" at 11683.96,1686.13 h60
  text "ANSI IPC-A-600F CLASS ->" at 11822.96,1686.13 h60
  text "X" at 13462.02,1686.13 h60
  text "2" at 13580.96,1686.14 h60
  text "1" at 13265.96,1684.64 h60
  text "3" at 13934.96,1684.64 h60
  text "X" at 11686.02,1526.64 h60
  text "UL 94V-0" at 11822.96,1526.64 h60
  text "X" at 12498.02,1526.64 h60
  text "RoHS" at 12634.96,1526.64 h60
  text "OTHER" at 13279.36,1526.64 h60
  text "PER ORDER" at 13676.42,1526.64 h60
  text "ADDITIONAL REQUIREMENTS:" at 11332.46,1385.64 h60
  text "MICROSECTION:" at 11407.23,1270.64 h60
  text "YES" at 12312.96,1270.64 h60
  text "REQUIRED" at 13174.46,1114.49 h60
  text "BARE BOARD ELEC. TEST:" at 11407.23,1111.64 h60
  text "NONE" at 12712.96,1111.64 h60
  text "PER ORDER" at 13766.46,1111.64 h60
  text "X" at 12587,1108 h60
  text "MANUFACTURER'S UL:" at 11407.23,954.64 h60
  text "RAIL" at 12572.96,950.35 h60
  text "METAL" at 13064.77,950.35 h60
  text "X" at 13440,950 h60
  text "SILK" at 13576.46,950.35 h60
M11 Gerber Information:
  lines w10: -292,-930.17 6308,-930.17 ; -292,-726.83 6310,-726.83 ; -292,-523.5 -292,-1133.5 3713,-1133.5 6310,-1133.5 6310,-523.5 -291.5,-523.5 -291.5,-1133.5 1284,-1133.5 ; 2173,-1133.5 2173,-523.5 ; 3440,-726.83 3440,-523.5 ; 4280,-726.83 4280,-523.5 ; 4902,-1140 4902,-937.17
  text "ALL ARTWORK VIEWED FROM TOP SIDE" at -228.5,-655.67 h60
  text "BOARD #:" at 2248,-655.67 h60
  text ".PRJ_Number" at 2793.5,-655.67 h60
  text "REV:" at 3638,-655.67 h60
  text ".PCB_Rev" at 3929.5,-655.67 h60
  text "SVN REV:" at 4476,-655.67 h60
  text ".VersionControl_RevNumber" at 4982,-655.67 h60
  text "LAYER NAME =" at -228.5,-858.49 h60
  text "PLOT NAME =" at -228.5,-1064.34 h60
  text ".plot_File_Name" at 577,-1064.34 h60
  text "GENERATED    :" at 2250,-1064.34 h60
  text ".Print_Date" at 3119.5,-1064.34 h60
  text ".Print_Time" at 3848.5,-1064.34 h60
  text "TEXAS INSTRUMENTS" at 5113,-1064.34 h60
M12 Stackup:
  lines w6: 11360,7460 13910,7460 ; 11360,7564.4 13910,7564.4 ; 11300,6975 ccw(c11334,6975) 11334,6941 13936,6941 ccw(c13936,6975) 13970,6975 13970,7681 ccw(c13936,7681) 13936,7715 11334,7715 ccw(c11334,7681) 11300,7681 11300,6975
  text "The Stackup Legend below this is static." at 11605.5,7874.5 h60
  text "If you change the stackup, update the Legend." at 11615.5,7784.5 h60
  text "Layer Stack Up Detail for: Ref_Design.PcbDoc" at 11360,7597.1 h57
  text "Layer" at 11360,7525.4 h24
  text "Gerber" at 12255.81,7525.4 h24
  text "Copper" at 12819.33,7525.4 h24
  text "Dielectric" at 13422.04,7525.4 h24
  text "Name" at 11360,7477.4 h24
  text "Document" at 12255.81,7477.4 h24
  text "Thickness" at 12819.33,7477.4 h24
  text "Material" at 13422.04,7477.4 h24
  text "Top Solder Mask" at 11360,7384.44 h34
  text "(.GTS)" at 12255.81,7384.44 h34
  text "Solder Resist" at 13422.04,7384.44 h34
  text "Top Layer" at 11360,7287.69 h34
  text "(.GTL)" at 12255.81,7287.69 h34
  text "1.4mil" at 12819.33,7287.69 h34
  text "FR-4" at 13422.04,7239.31 h34
  text "Bottom Layer" at 11360,7190.94 h34
  text "(.GBL)" at 12255.81,7190.94 h34
  text "1.4mil" at 12819.33,7190.94 h34
  text "Bottom Solder Mask" at 11360,7094.19 h34
  text "(.GBS)" at 12255.81,7094.19 h34
  text "Solder Resist" at 13422.04,7094.19 h34
M14 Component Bodies Bottom:
  text ".Layer_Name" at 577,-858.49 h60
Drill Drawing:
  text ".legend" at 3019.5,1350.5 h60
  text "Drill Table" at 3044.5,1165.5 h60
